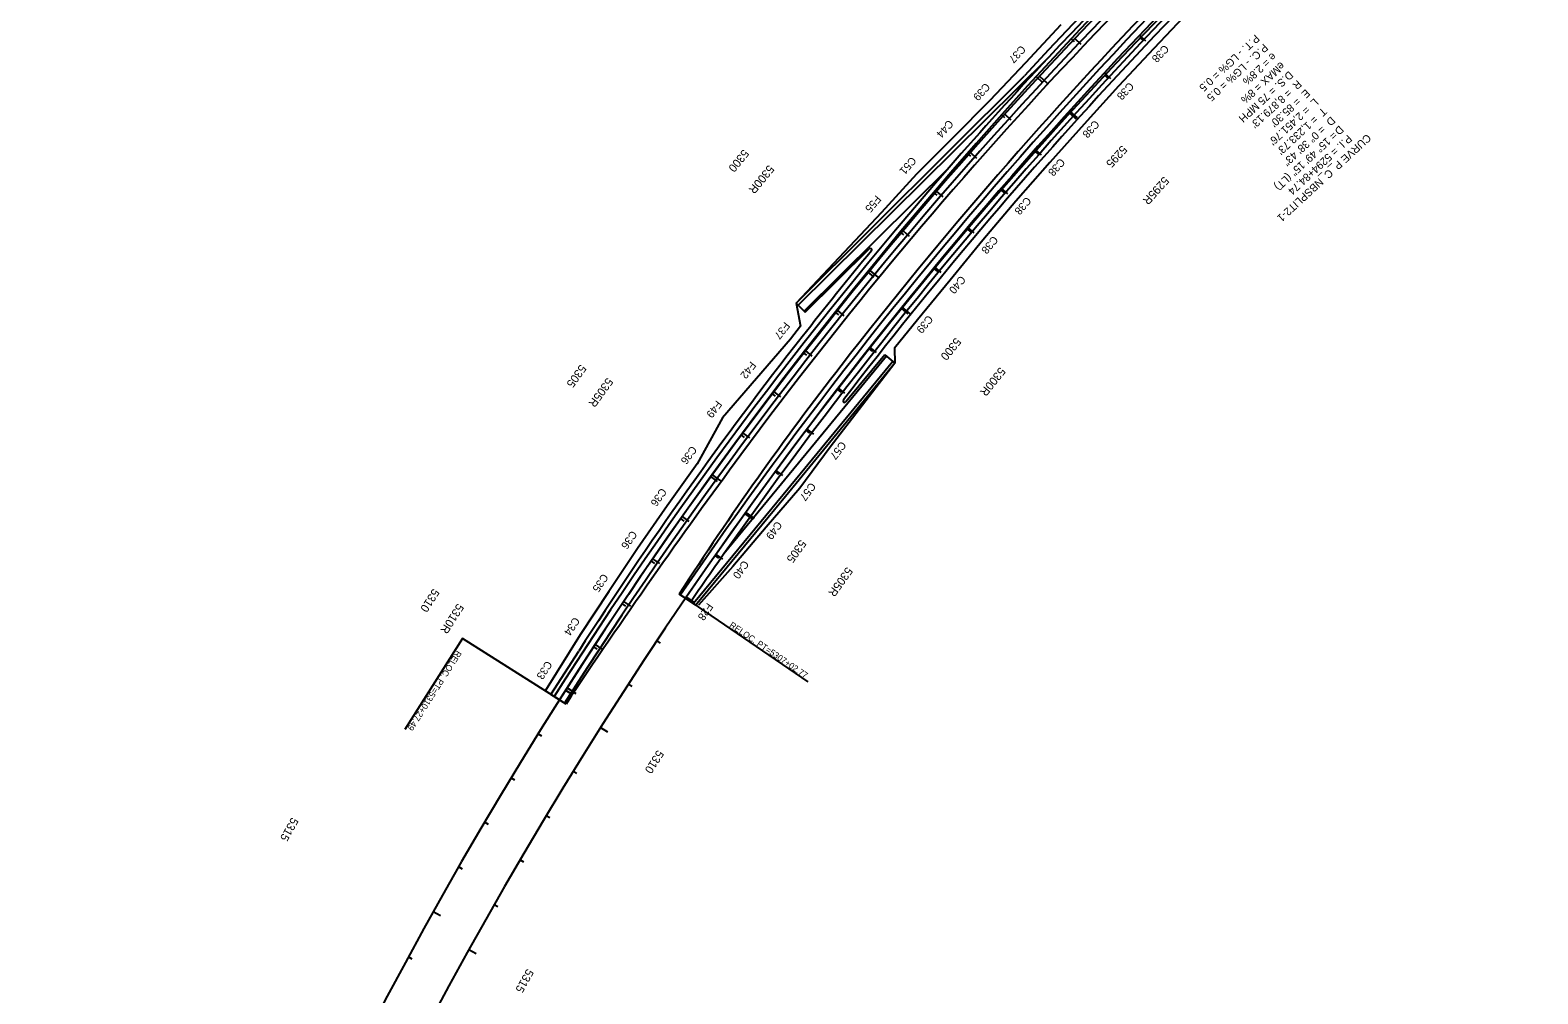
# Model space of a CAD drawing. Extents: x 2160877 to 2175861, y 601747 to 617724.
# Drawn here: x 2161211 to 2164133, y 603603 to 605470 of the extents above; entities that cross this region are included whole.
import ezdxf

# ---------------------------------------------------------------- set-up
doc = ezdxf.new("R2010")
doc.units = 0
for name, color, linetype in [('RD_HC_Cl', 7, 'Continuous'), ('RD_HC_CL_Rel', 7, 'Continuous'), ('RD_HC_Data_Rel', 7, 'Continuous'), ('RD_HC_Data_Tic', 7, 'Continuous'), ('RD_HC_Data_Tic_Rel', 7, 'Continuous'), ('RD_HC_TX_Rel_Sta50', 7, 'Continuous'), ('RD_HC_TX_StaOther', 7, 'Continuous'), ('RD_PD_CstnLmt', 7, 'Continuous'), ('RD_PD_CstnLmt_TX', 7, 'Continuous'), ('RD_PD_Final_LnLine', 7, 'Continuous'), ('RD_PD_Final_TrvlWay', 7, 'Continuous')]:
    doc.layers.add(name, color=color, linetype=linetype)

msp = doc.modelspace()

# ---------------------------------------------------------------- linework, layer by layer
at = {"layer": 'RD_HC_Cl'}
for radius in [8641.9, 8545.9]:
    msp.add_arc((2169535, 599544.7), radius, 132.71947, 164.41949, dxfattribs=at)
at = {"layer": 'RD_HC_CL_Rel'}
for centre, radius, end in [((2169810, 599356.6), 8879.1, 145.62858), ((2169305.2, 599690.4), 8369.8, 147.62243)]:
    msp.add_arc(centre, radius, 129.80773, end, dxfattribs=at)
at = {"layer": 'RD_HC_Data_Rel'}
msp.add_line((2162481.2, 604369.4), (2162717.9, 604207.5), dxfattribs=at)
msp.add_lwpolyline([(2162236.6, 604172.5), (2162048.9, 604291.4), (2161937, 604114.9)], dxfattribs=at)
at = {"layer": 'RD_HC_Data_Tic'}
for p, q in [((2163228.5, 605453.3), (2163234.3, 605447.8)), ((2163362.5, 605455.2), (2163368.3, 605449.6)), ((2163160.5, 605379.9), (2163172.3, 605369.1)), ((2163293.8, 605382.6), (2163299.6, 605377.1)), ((2163093.4, 605305.7), (2163099.4, 605300.4)), ((2163225.9, 605309.1), (2163237.7, 605298.3)), ((2163027.2, 605230.8), (2163033.2, 605225.6)), ((2163158.9, 605234.9), (2163164.9, 605229.6)), ((2162961.9, 605155.1), (2162967.9, 605149.9)), ((2163092.7, 605159.9), (2163098.8, 605154.7)), ((2163027.5, 605084.1), (2163033.6, 605079)), ((2162897.4, 605078.7), (2162903.5, 605073.6)), ((2162833.8, 605001.5), (2162846.2, 604991.4)), ((2162963.1, 605007.6), (2162969.3, 605002.5)), ((2162771.1, 604923.6), (2162777.4, 604918.6)), ((2162899.6, 604930.3), (2162912.1, 604920.3)), ((2162837.1, 604852.3), (2162843.3, 604847.4)), ((2162709.3, 604845), (2162715.6, 604840.1)), ((2162648.4, 604765.7), (2162654.8, 604760.8)), ((2162775.4, 604773.6), (2162781.8, 604768.7)), ((2162588.5, 604685.6), (2162594.9, 604680.9)), ((2162714.7, 604694.1), (2162721.1, 604689.3)), ((2162529.5, 604604.9), (2162542.4, 604595.5)), ((2162654.9, 604614), (2162661.4, 604609.2)), ((2162596.1, 604533.1), (2162609.1, 604523.8)), ((2162471.4, 604523.5), (2162477.9, 604518.9)), ((2162414.2, 604441.4), (2162420.8, 604436.9)), ((2162538.2, 604451.6), (2162544.7, 604447)), ((2162358.1, 604358.7), (2162364.7, 604354.2)), ((2162481.2, 604369.4), (2162487.8, 604364.9)), ((2162302.8, 604275.3), (2162309.5, 604271)), ((2162425.3, 604286.5), (2162431.9, 604282.1)), ((2162248.6, 604191.3), (2162262.1, 604182.7)), ((2162370.3, 604203), (2162377, 604198.6)), ((2162316.3, 604118.8), (2162329.8, 604110.3)), ((2162195.3, 604106.7), (2162202.1, 604102.5)), ((2162263.2, 604034.1), (2162270, 604029.9)), ((2162143, 604021.5), (2162149.8, 604017.3)), ((2162211.2, 603948.7), (2162218, 603944.5)), ((2162091.7, 603935.6), (2162098.6, 603931.6)), ((2162160.2, 603862.7), (2162167.1, 603858.6)), ((2162041.4, 603849.2), (2162048.3, 603845.2)), ((2162110.1, 603776.1), (2162117.1, 603772.1)), ((2161992.1, 603762.2), (2162006, 603754.4)), ((2162061.1, 603688.9), (2162075.1, 603681.2)), ((2161943.8, 603674.6), (2161950.8, 603670.8))]:
    msp.add_line(p, q, dxfattribs=at)
at = {"layer": 'RD_HC_Data_Tic_Rel'}
for p, q in [((2163235.8, 605453.8), (2163247.4, 605442.8)), ((2163361.2, 605460), (2163372.8, 605449)), ((2163167.4, 605380.9), (2163182.1, 605367.3)), ((2163292.8, 605387), (2163304.6, 605376.1)), ((2163099.8, 605307.2), (2163111.7, 605296.4)), ((2163225.3, 605313.2), (2163240.2, 605299.8)), ((2163033.2, 605232.6), (2163045.2, 605222)), ((2163158.7, 605238.7), (2163170.7, 605228.1)), ((2162967.4, 605157.3), (2162979.5, 605146.8)), ((2163092.8, 605163.4), (2163104.9, 605152.9)), ((2163027.9, 605087.4), (2163040.1, 605077)), ((2162902.6, 605081.2), (2162914.8, 605070.9)), ((2162838.6, 605004.3), (2162854.1, 604991.6)), ((2162963.8, 605010.6), (2162976.1, 605000.4)), ((2162775.6, 604926.7), (2162788.1, 604916.7)), ((2162900.5, 604933.1), (2162916.1, 604920.6)), ((2162838.2, 604855), (2162850.7, 604845.1)), ((2162713.5, 604848.3), (2162726.1, 604838.4)), ((2162652.3, 604769.2), (2162665.1, 604759.4)), ((2162776.7, 604776.1), (2162789.3, 604766.3)), ((2162592.1, 604689.3), (2162605, 604679.8)), ((2162716.1, 604696.6), (2162728.9, 604686.9)), ((2162656.4, 604616.3), (2162669.3, 604606.9)), ((2162532.9, 604608.7), (2162549.1, 604597)), ((2162474.6, 604527.5), (2162487.7, 604518.2)), ((2162597.6, 604535.4), (2162613.9, 604523.8)), ((2162417.3, 604445.5), (2162430.5, 604436.4)), ((2162539.7, 604453.9), (2162552.8, 604444.7)), ((2162361, 604362.9), (2162374.3, 604354)), ((2162482.8, 604371.7), (2162496, 604362.6)), ((2162305.7, 604279.6), (2162319, 604270.8)), ((2162251.3, 604195.6), (2162268.2, 604184.9))]:
    msp.add_line(p, q, dxfattribs=at)
at = {"layer": 'RD_PD_CstnLmt'}
for p, q in [((2163457.1, 605506.3), (2163388.7, 605434)), ((2163208.3, 605480), (2163139.9, 605406.4)), ((2163388.7, 605434), (2163320.6, 605361.3)), ((2163139.9, 605406.4), (2163070.9, 605333.4)), ((2163320.6, 605361.3), (2163253.7, 605287.5)), ((2163070.9, 605333.4), (2162999.9, 605262)), ((2163253.7, 605287.5), (2163187, 605213.6)), ((2162999.9, 605262), (2162928.5, 605190.9)), ((2163187, 605213.6), (2163121.5, 605138.6)), ((2162928.5, 605190.9), (2162860.7, 605116.4)), ((2162860.7, 605116.4), (2162695.3, 604940.8)), ((2163121.5, 605138.6), (2163057.1, 605062.7)), ((2163057.1, 605062.7), (2162994.2, 604985.4)), ((2162994.2, 604985.4), (2162930.9, 604908.6)), ((2162684.3, 604871.1), (2162618.9, 604794.7)), ((2162886.8, 604824.9), (2162761.6, 604662.3)), ((2162618.9, 604794.7), (2162552.6, 604718.7)), ((2162552.6, 604718.7), (2162503.6, 604630)), ((2162761.6, 604662.3), (2162702.7, 604582.3)), ((2162503.6, 604630), (2162445.2, 604548.3)), ((2162702.7, 604582.3), (2162637.1, 604507.1)), ((2162445.2, 604548.3), (2162388, 604465.8)), ((2162637.1, 604507.1), (2162572.7, 604430.8)), ((2162388, 604465.8), (2162332.1, 604382.3)), ((2162572.7, 604430.8), (2162505.9, 604355.8)), ((2162332.1, 604382.3), (2162277.1, 604298.3)), ((2162277.1, 604298.3), (2162209.4, 604190.8))]:
    msp.add_line(p, q, dxfattribs=at)
for points in [[(2162695.3, 604940.8), (2162703.9, 604896.1), (2162684.3, 604871.1)], [(2162930.9, 604908.6), (2162886.4, 604853.6), (2162886.8, 604824.9)]]:
    msp.add_lwpolyline(points, dxfattribs=at)
at = {"layer": 'RD_PD_Final_LnLine'}
for p, q in [((2162699.5, 604937), (2163184.6, 605417)), ((2162695.3, 604940.8), (2163137.8, 605381.3)), ((2162710.7, 604925.6), (2162991.9, 605203.8)), ((2162712.8, 604923.5), (2162836.9, 605046.2)), ((2162501, 604355.8), (2162469, 604377.5)), ((2162249.4, 604164.1), (2162220.2, 604182.8))]:
    msp.add_line(p, q, dxfattribs=at)
for points in [[(2162882.9, 604828), (2162670.6, 604569.9), (2162496.6, 604358.9)], [(2162870.6, 604838.2), (2162658.3, 604580.1), (2162555.5, 604455.4)]]:
    msp.add_lwpolyline(points, dxfattribs=at)
for centre, radius, start, end in [((2169810, 599356.6), 8891.1, 129.80773, 145.62858), ((2169810, 599356.6), 8867.1, 129.80773, 144.89859), ((2169305.2, 599690.4), 8357.8, 129.80773, 147.62243), ((2169305.2, 599690.4), 8381.8, 129.80773, 136.90521), ((2169305.2, 599690.4), 8381.8, 136.90521, 138.86967), ((2169305.2, 599690.4), 8381.8, 138.86967, 147.62243), ((2169810, 599356.6), 8867.1, 144.89859, 145.62858), ((2169810, 599356.6), 8855.1, 145.60256, 145.62858)]:
    msp.add_arc(centre, radius, start, end, dxfattribs=at)
at = {"layer": 'RD_PD_Final_TrvlWay'}
for p, q in [((2162695.3, 604940.8), (2162712.8, 604923.5)), ((2162867.2, 604840.9), (2162791.7, 604749.7)), ((2162220.2, 604182.8), (2162274.1, 604266.9))]:
    msp.add_line(p, q, dxfattribs=at)
for points in [[(2162886.8, 604824.9), (2162674.5, 604566.7), (2162503.3, 604359.2)], [(2162867.2, 604840.9), (2162886.8, 604824.9)]]:
    msp.add_lwpolyline(points, dxfattribs=at)
for centre, radius, start, end in [((2169810, 599356.6), 8901.1, 129.80773, 142.13894), ((2169305.2, 599690.4), 8391.8, 129.80773, 137.30123), ((2169305.2, 599690.4), 8347.8, 129.80773, 143.57306), ((2169810, 599356.6), 8857.1, 131.47407, 142.45996), ((2169305.2, 599690.4), 8391.8, 140.37636, 141.83733), ((2162839.1, 605044.1), 3, 320.3767, 134.6957), ((2168840.4, 600055.8), 7800.6, 141.83733, 147.32681), ((2167652.2, 601034.1), 6168, 142.13894, 147.17611), ((2162789.3, 604751.6), 3, 142.46, 320.3646), ((2172511.3, 597324.3), 12332.5, 143.57306, 146.31587)]:
    msp.add_arc(centre, radius, start, end, dxfattribs=at)

# ---------------------------------------------------------------- texts
at = {"layer": 'RD_HC_Data_Rel'}
for s, height, rotation, p in [('P.T. - LG% = 0.5', 15, 222.7195, (2163585.5, 605462.3)), ('P.C. - LG% = 0.5', 15, 222.7195, (2163601.8, 605444.6)), ('eMAX = 8%', 15, 222.7195, (2163634.4, 605409.4)), ('e = 2.8%', 15, 222.7195, (2163618.1, 605427)), ('D.S. = 75 MPH', 15, 222.7195, (2163650.7, 605391.7)), ("R  = 8,879.13'", 15, 222.7195, (2163666.9, 605374.1)), ("E  = 85.30'", 15, 222.7195, (2163683.2, 605356.5)), ("L  = 2,451.76'", 15, 222.7195, (2163699.5, 605338.8)), ("T  = 1,233.73'", 15, 222.7195, (2163715.8, 605321.2)), ('D  = 0%%d 38\' 43"', 15, 222.7195, (2163732.1, 605303.6)), ('   = 15%%d 49\' 15" (LT)', 15, 222.7195, (2163748.4, 605286)), ('CURVE P_C_NBSPLIT2-1', 15, 222.7195, (2163801.6, 605269.8)), ('P.I. = 5294+84.74', 15, 222.7195, (2163764.6, 605268.3)), ('D ', 15, 222.7195, (2163748.4, 605286)), ('RELOC. PT=5307+02.77', 12, 325.6286, (2162564.9, 604314.6)), ('RELOC. PT=5310+27.49', 12, 237.6224, (2162037.5, 604269.1))]:
    msp.add_text(s, height=height, rotation=rotation, dxfattribs=at).set_placement(p)
at = {"layer": 'RD_HC_TX_Rel_Sta50'}
for s, rotation, p in [('5300R', 230.5887, (2162642.1, 605209.9)), ('5295R', 227.8673, (2163408.2, 605187.4)), ('5305R', 234.0115, (2162329.1, 604797.8)), ('5300R', 231.0937, (2163090.4, 604818.1)), ('5305R', 234.3201, (2162793.5, 604431)), ('5310R', 237.4342, (2162039.1, 604360.3))]:
    msp.add_text(s, height=16, rotation=rotation, dxfattribs=at).set_placement(p)
at = {"layer": 'RD_HC_TX_StaOther'}
for s, rotation, p in [('5300', 230.8442, (2162593.1, 605240.1)), ('5295', 227.5832, (2163327, 605247.7)), ('5300', 230.9354, (2163004.4, 604875.4)), ('5305', 234.1592, (2162277.2, 604823.4)), ('5305', 234.2877, (2162703.6, 604484)), ('5310', 237.4741, (2161991.7, 604389.2)), ('5310', 237.6399, (2162426.7, 604076.5)), ('5315', 240.7891, (2161717.7, 603946)), ('5315', 240.9921, (2162173.7, 603652.6))]:
    msp.add_text(s, height=16, rotation=rotation, dxfattribs=at).set_placement(p)
at = {"layer": 'RD_PD_CstnLmt_TX'}
for s, rotation, p in [('C37', 227.166, (2163131.1, 605441.6)), ('C38', 226.5767, (2163408.9, 605442.6)), ('C39', 227.8505, (2163061.9, 605368.8)), ('C38', 227.222, (2163340.8, 605370.1)), ('C44', 228.5351, (2162990.6, 605297.2)), ('C38', 227.8673, (2163273.8, 605296.6)), ('C51', 229.2196, (2162918.6, 605225.8)), ('C38', 228.5125, (2163207, 605222.9)), ('F55', 229.9042, (2162850.2, 605151.1)), ('C38', 229.1578, (2163141.5, 605148.1)), ('C38', 229.8031, (2163077, 605072.4)), ('C40', 230.4484, (2163014, 604995.4)), ('C39', 231.0937, (2162950.6, 604918.8)), ('F37', 231.9578, (2162673.1, 604905.8)), ('F42', 232.6424, (2162607.3, 604829.3)), ('F49', 233.3269, (2162541, 604753.6)), ('C36', 234.0115, (2162492.3, 604665.7)), ('C57', 233.0295, (2162782, 604674.6)), ('C57', 233.6748, (2162723, 604594.8)), ('C36', 234.696, (2162433.6, 604584.1)), ('C36', 235.3806, (2162376.2, 604501.5)), ('C49', 234.3201, (2162657.4, 604519.9)), ('C40', 234.9654, (2162592.9, 604443.9)), ('C35', 236.0651, (2162320.2, 604418.2)), ('F28', 235.6107, (2162523.4, 604361.4)), ('C34', 236.7497, (2162264.8, 604334)), ('C33', 237.4342, (2162211.2, 604249.3))]:
    msp.add_text(s, height=15, rotation=rotation, dxfattribs=at).set_placement(p)

doc.saveas('drawing.dxf')
